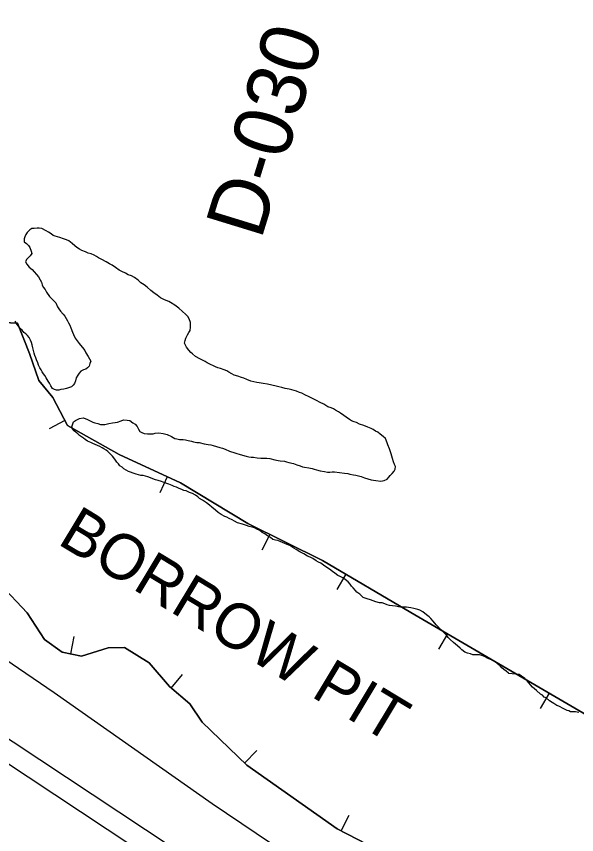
# Model space of a CAD drawing. Extents: x 3263578 to 3301413, y 764927 to 798602.
# Drawn here: x 3282551 to 3283343, y 780646 to 781803 of the extents above; entities that cross this region are included whole.
import ezdxf

# ---------------------------------------------------------------- set-up
doc = ezdxf.new("R2010")
doc.units = 0
for name, color, linetype in [('V-BORW-IDEN', 7, 'Continuous'), ('V-BORW-LINE', 7, 'Continuous'), ('V-LEVE-TOET', 7, 'Continuous'), ('V-RIVR-RANG-IDEN', 7, 'Continuous'), ('V-SITE-VEGE', 7, 'Continuous'), ('V-SURV-LINE', 7, 'Continuous')]:
    doc.layers.add(name, color=color, linetype=linetype)

msp = doc.modelspace()

# ---------------------------------------------------------------- linework, layer by layer
at = {"layer": 'V-BORW-LINE'}
for p, q in [((3282619.2, 781231.5), (3282597.1, 781219.8)), ((3282763.8, 781151.8), (3282753.3, 781129.2)), ((3282908.9, 781070.4), (3282897.8, 781048)), ((3283016.2, 781014.1), (3283003.5, 780992.5)), ((3283159.9, 780929.7), (3283147.3, 780908.1)), ((3282627.4, 780901.4), (3282632.3, 780926)), ((3282769.5, 780853.1), (3282785.6, 780872.2)), ((3283303.7, 780845.7), (3283291.1, 780824.1)), ((3282873.2, 780747), (3282890.7, 780764.9)), ((3283009.6, 780651.4), (3283021, 780673.6))]:
    msp.add_line(p, q, dxfattribs=at)
for points in [[(3281936.7, 781679), (3281970.5, 781688), (3282101.7, 781597.5), (3282317.6, 781460.6), (3282365.2, 781493), (3282394, 781492.1), (3282442.1, 781462.3), (3282458.7, 781427.8), (3282449.4, 781377.6), (3282437.8, 781319.2), (3282438.2, 781301.5), (3282456.7, 781289.2), (3282475.5, 781286.2), (3282490, 781341.3), (3282512.8, 781370.8), (3282552.3, 781369), (3282569.1, 781326.3), (3282582.3, 781288), (3282602, 781263.8), (3282622.9, 781224.4), (3282695.9, 781183.2), (3282782.6, 781143.1), (3282877.6, 781085.9), (3282983.5, 781033.3)], [(3282983.5, 781033.3), (3282877.6, 781085.9), (3282782.6, 781143.1), (3282695.9, 781183.2), (3282622.9, 781224.4), (3282602, 781263.8), (3282582.3, 781288), (3282569.1, 781326.3), (3282552.3, 781369), (3282512.8, 781370.8), (3282490, 781341.3), (3282475.5, 781286.2), (3282456.7, 781289.2), (3282438.2, 781301.5), (3282437.8, 781319.2), (3282449.4, 781377.6), (3282458.7, 781427.8), (3282442.1, 781462.3), (3282394, 781492.1), (3282365.2, 781493), (3282317.6, 781460.6), (3282101.7, 781597.5), (3281970.5, 781688), (3281936.7, 781679)], [(3282983.5, 781033.3), (3283108.4, 780959.8), (3283356.9, 780814.6), (3283428.4, 780772.9), (3283485.5, 780717.2), (3283537, 780681.4), (3283609.2, 780664), (3283697.2, 780660.9), (3283794.4, 780670.6), (3283906.6, 780663.8), (3283981.7, 780643.3)], [(3283981.7, 780643.3), (3283906.6, 780663.8), (3283794.4, 780670.6), (3283697.2, 780660.9), (3283609.2, 780664), (3283537, 780681.4), (3283485.5, 780717.2), (3283428.4, 780772.9), (3283356.9, 780814.6), (3283108.4, 780959.8), (3282983.5, 781033.3)], [(3282813.5, 780805.1), (3282795.8, 780830.9), (3282767, 780855.2), (3282738.3, 780888.9), (3282703.5, 780910.5), (3282680.4, 780909.9), (3282642.6, 780898.4), (3282615.3, 780903.8), (3282590.4, 780921.7), (3282566, 780959.5), (3282527.5, 781000.1)], [(3282527.5, 781000.1), (3282566, 780959.5), (3282590.4, 780921.7), (3282615.3, 780903.8), (3282642.6, 780898.4), (3282680.4, 780909.9), (3282703.5, 780910.5), (3282738.3, 780888.9), (3282767, 780855.2), (3282795.8, 780830.9), (3282813.5, 780805.1)], [(3283144.6, 780581.6), (3283004.1, 780654.2), (3282876.4, 780744), (3282813.5, 780805.1)], [(3282813.5, 780805.1), (3282876.4, 780744), (3283004.1, 780654.2), (3283144.6, 780581.6)]]:
    msp.add_lwpolyline(points, dxfattribs=at)
at = {"layer": 'V-LEVE-TOET'}
msp.add_lwpolyline([(3282972.3, 780592), (3282827.2, 780689.6), (3282604, 780846.6), (3282423.9, 780969.1), (3282234.6, 781089.3), (3282039.4, 781214), (3281861, 781327.2), (3281775.1, 781380.4), (3281661.9, 781445.9), (3281571.4, 781498), (3281456.3, 781581.8), (3281323.5, 781672.6), (3281178.8, 781772.9), (3281016.6, 781873.4), (3280802.7, 782020.5), (3280772.2, 782036.9), (3280719.9, 782063), (3280609.7, 782132.1), (3280537.9, 782178.1), (3280496.4, 782202.5)], dxfattribs=at)
at = {"layer": 'V-SITE-VEGE'}
for points in [[(3282930.8, 781276.7), (3282926, 781278.1), (3282921.7, 781279), (3282918, 781279.9), (3282911.6, 781281.3), (3282905.4, 781282.7), (3282899.3, 781283.9), (3282894, 781284.8), (3282890.5, 781285.4), (3282886.2, 781286.2), (3282881.9, 781287.1), (3282876.4, 781289.6), (3282872.1, 781291.3), (3282868.9, 781292.1), (3282863.8, 781294.1), (3282858.5, 781295.7), (3282855.1, 781297.4), (3282851.1, 781299.9), (3282848.2, 781301.5), (3282844.4, 781303.2), (3282839.1, 781305.1), (3282835.6, 781306), (3282832.2, 781307.4), (3282829.3, 781308.8), (3282825, 781310.7), (3282820.5, 781313.2), (3282817.3, 781314.8), (3282813.6, 781316.8), (3282810.1, 781318.7), (3282804, 781322), (3282799.5, 781325.5), (3282797.4, 781327.7), (3282794.2, 781330.7), (3282791.3, 781335), (3282788.2, 781341), (3282789.1, 781344.4), (3282790.2, 781347.9), (3282792.4, 781352.4), (3282794.6, 781356.1), (3282796.3, 781358.8), (3282796.6, 781363.3), (3282796.7, 781370), (3282794.9, 781375.1), (3282792.8, 781378.4), (3282789.6, 781381.6), (3282785.4, 781385.7), (3282780.1, 781390.1), (3282774.8, 781394.4), (3282768.7, 781398.3), (3282766.1, 781399.9), (3282762.6, 781401.3), (3282759.1, 781402.4), (3282754.6, 781404.9), (3282749.6, 781408.5), (3282745.1, 781411.8), (3282740.6, 781415.3), (3282735.6, 781419.9), (3282731.3, 781423.2), (3282726.8, 781426.2), (3282722.6, 781430), (3282717.8, 781433.6), (3282713.6, 781435.8), (3282708.8, 781437.5), (3282704.8, 781439.7), (3282699.5, 781442.2), (3282696, 781444.1), (3282691, 781447.9), (3282686.2, 781451.2), (3282682.2, 781453.1), (3282677.5, 781455.9), (3282671.6, 781458.9), (3282666.8, 781461.6), (3282663.9, 781463.3), (3282660.5, 781465.2), (3282656.5, 781466.9), (3282652.2, 781468), (3282648.2, 781470), (3282643.4, 781471.6), (3282639.7, 781473.6), (3282636.3, 781476), (3282633.3, 781478.5), (3282629.4, 781481.7), (3282624.6, 781485.6), (3282621.4, 781487), (3282617.2, 781488.4), (3282612.1, 781490), (3282605.7, 781492.3), (3282602.8, 781493.1), (3282599.6, 781495.3), (3282595.9, 781497.8), (3282592.7, 781499.4), (3282586.8, 781502.7), (3282583.1, 781503.3), (3282579.9, 781503.4), (3282575.9, 781502.9), (3282572.7, 781502.9), (3282569.7, 781501.1), (3282566.1, 781497.1), (3282564.2, 781494.5), (3282562.6, 781491.3), (3282561.5, 781488.1)], [(3282561.5, 781488.1), (3282561.9, 781484.1), (3282564.9, 781481.9), (3282567.8, 781478.9), (3282569.6, 781475.9), (3282571.7, 781471.1), (3282572.4, 781467.6), (3282570.2, 781464.4), (3282568, 781462), (3282564.8, 781458.9), (3282563.4, 781455.7), (3282565.2, 781452.4), (3282568.9, 781448.4), (3282572.9, 781444.8), (3282576, 781441.6), (3282578.9, 781437.8), (3282581.8, 781434.5), (3282584.4, 781430.5), (3282586.3, 781427.2), (3282587.3, 781423.5), (3282588.6, 781420.2), (3282591.2, 781416.7), (3282593.3, 781412.9), (3282597.5, 781407), (3282602.8, 781401.8), (3282606.5, 781398), (3282609, 781392.1), (3282610.9, 781389.4), (3282613.2, 781386.1), (3282616.7, 781381.8), (3282619, 781379.1), (3282620.8, 781375.8), (3282622.9, 781372.3), (3282624.2, 781369.4), (3282626.1, 781366.1), (3282627.4, 781362.6), (3282629.9, 781356.2), (3282631.2, 781352.9), (3282633.8, 781348.1), (3282636.4, 781344), (3282639.6, 781340.2), (3282641.4, 781337.8), (3282644.3, 781334.5), (3282647.2, 781330.5), (3282649, 781327.2), (3282652.2, 781321.8), (3282655.8, 781315.3), (3282654.7, 781312.1), (3282653.6, 781308.1), (3282651.4, 781305.8), (3282648.7, 781304.2), (3282645.5, 781302.9), (3282642, 781301.1), (3282639.5, 781298.2), (3282637.6, 781295.5), (3282635.4, 781291.8), (3282634.3, 781287.5), (3282632.6, 781283.8), (3282631, 781281.2), (3282628.5, 781279.1), (3282624.5, 781277.5), (3282621.3, 781276.5), (3282617.8, 781275.7), (3282613.7, 781275.3), (3282610.8, 781274.5), (3282607.6, 781274.3), (3282604.6, 781275.4), (3282601.7, 781276.8), (3282599.4, 781280.6), (3282597.5, 781284.1), (3282595.7, 781287.3), (3282592.8, 781291.6), (3282591, 781295.1), (3282588.9, 781297.6), (3282587.1, 781300.3), (3282585.5, 781303), (3282583.7, 781306), (3282582.1, 781309.7), (3282581.1, 781313), (3282579.3, 781317), (3282578.3, 781320), (3282576.7, 781323.5), (3282575.7, 781326.7), (3282574.7, 781330.2), (3282573.9, 781334), (3282572.9, 781338.5), (3282571.9, 781341.8), (3282570.6, 781345), (3282568.5, 781348.8), (3282566.4, 781351.5), (3282563.8, 781353.9), (3282561.4, 781356.1), (3282559, 781359.1), (3282556.6, 781361.3), (3282554.5, 781363.4), (3282551.6, 781367.2), (3282548.8, 781371.8)], [(3282833.5, 781194.9), (3282838.3, 781193.5), (3282842, 781192.1), (3282846, 781190.7), (3282852.1, 781187.9), (3282859.3, 781185.9), (3282862.5, 781184.8), (3282865.7, 781184), (3282870.2, 781182.3), (3282875.3, 781181.2), (3282879.3, 781180.3), (3282882.5, 781179.7), (3282885.7, 781179.4), (3282890.8, 781178.8), (3282896.1, 781178.4), (3282899.4, 781178.4), (3282904.7, 781178.3), (3282909, 781177.7), (3282915.9, 781176), (3282920.5, 781174.9), (3282923.7, 781174.3), (3282929.5, 781173.9), (3282932.7, 781173.1), (3282935.7, 781172), (3282942.3, 781170.5), (3282947.1, 781168.6), (3282951.7, 781167.2), (3282954.9, 781166), (3282958.1, 781165.5), (3282964.2, 781164.6), (3282968.8, 781163.7), (3282971.7, 781162.6), (3282975.1, 781161.5), (3282980, 781160.3), (3282986.1, 781159.4), (3282990.4, 781158.6), (3282993.6, 781158.5), (3282997.1, 781158.7), (3283000.3, 781158.7), (3283007.5, 781158), (3283014.7, 781157.1), (3283019, 781156.3), (3283022.2, 781155.4), (3283027.3, 781154.8), (3283030.5, 781154.2), (3283037.9, 781152.2), (3283042.7, 781150.6), (3283047.5, 781149.1), (3283052.3, 781147.7), (3283058.7, 781146.6), (3283066, 781145.7), (3283070.5, 781146.4), (3283074.8, 781148.7), (3283077.3, 781151.1), (3283079.2, 781153.5), (3283081.9, 781156.4), (3283084.9, 781159.8), (3283086.3, 781162.8), (3283086.6, 781166.2), (3283085.3, 781169.2), (3283083.8, 781173), (3283082.2, 781177.5), (3283080.5, 781184.5), (3283077.9, 781191.5), (3283075.8, 781196.9), (3283074.8, 781199.9), (3283072.2, 781205.8), (3283069, 781208.8), (3283064.8, 781212.1), (3283061.4, 781214.8), (3283058.4, 781216.5), (3283055, 781218.7), (3283052.1, 781220), (3283047.5, 781222), (3283041.7, 781224.2), (3283035.8, 781226.4), (3283031.6, 781228.4), (3283028.1, 781229.8), (3283024.4, 781231.2), (3283021.5, 781232.8), (3283016.7, 781236.4), (3283013.5, 781238.5), (3283009, 781241.8), (3283005.8, 781243.8), (3283001.6, 781246), (3282998.7, 781247.9), (3282995.7, 781249.3), (3282990.9, 781250.9), (3282988, 781252.8), (3282985.1, 781254.5), (3282980.3, 781257), (3282975, 781259.5), (3282969.4, 781262.5), (3282963.8, 781265.3), (3282959.3, 781267.5), (3282954, 781270), (3282950.8, 781271.1), (3282946.5, 781272.7), (3282940.1, 781274.7), (3282936.1, 781275.6), (3282930.8, 781276.7)], [(3282784.6, 781133.8), (3282780.6, 781135.4), (3282777.2, 781137.1), (3282773.7, 781138.2), (3282770.8, 781139.6), (3282766, 781141.5), (3282760.4, 781143.5), (3282755.9, 781145.2), (3282751.1, 781146.8), (3282747.1, 781147.7), (3282743.6, 781149.1), (3282740.4, 781150.2), (3282736.4, 781151.9), (3282733.2, 781152.7), (3282730, 781153.6), (3282726.5, 781153.9), (3282723.3, 781154.8), (3282719.9, 781155.6), (3282715.6, 781157), (3282711.9, 781158.4), (3282709, 781159.5), (3282706, 781161.2), (3282702.6, 781163.1), (3282700.2, 781165.3), (3282697, 781167.5), (3282694.9, 781170.2), (3282692.8, 781172.6), (3282689.7, 781176.9), (3282686.5, 781181), (3282684.1, 781183.4), (3282679.9, 781187.5), (3282677.5, 781189.7), (3282674.3, 781191.4), (3282671.7, 781193), (3282668.5, 781194.9), (3282665.3, 781196.3), (3282662.1, 781197.7), (3282658.9, 781198.8), (3282655.7, 781200.2), (3282651.2, 781202.4), (3282647.8, 781204.6), (3282645.4, 781206.5), (3282642.7, 781208.4), (3282640.1, 781210.3), (3282637.7, 781212.5), (3282635.3, 781214.4), (3282632.4, 781216.9), (3282629.8, 781219.6), (3282629, 781222.6), (3282630.1, 781225.5), (3282631.5, 781229.5), (3282634.2, 781231.3), (3282637.2, 781232.9), (3282639.9, 781234.4), (3282645, 781235.2), (3282647.9, 781234.3), (3282651.4, 781232.9), (3282654.1, 781231.3), (3282658.6, 781229.1), (3282661.5, 781228), (3282665.8, 781227.1), (3282669.8, 781226), (3282675.7, 781225.6), (3282681.3, 781227.4), (3282686.4, 781228.1), (3282690.4, 781228.6), (3282693.7, 781229.1), (3282698.8, 781231.2), (3282702, 781232.2), (3282707.1, 781232.1), (3282710.8, 781231.5), (3282715.3, 781228.2), (3282718.8, 781226.3), (3282721.4, 781223.1), (3282723.2, 781219), (3282725.3, 781216), (3282728, 781214.4), (3282731.4, 781213.3), (3282736, 781212.7), (3282739.7, 781212.6), (3282744, 781212.8), (3282747, 781213.6), (3282752.1, 781213.8), (3282758.2, 781212.9), (3282763.6, 781211.7), (3282769.7, 781208.7), (3282774.7, 781206.2), (3282777.6, 781205.4), (3282781.1, 781204.8), (3282786.2, 781204.4), (3282789.9, 781204.1), (3282793.4, 781203), (3282798.2, 781202.1), (3282801.2, 781201.3), (3282805.7, 781200.4), (3282808.9, 781200.3), (3282816.1, 781198.4), (3282821.7, 781197.5), (3282825.7, 781196.9), (3282828.9, 781196), (3282833.5, 781194.9)], [(3283168.6, 780917.6), (3283163.9, 780921.7), (3283161.2, 780924.4), (3283158.6, 780927.7), (3283154.9, 780931.5), (3283152.5, 780933.9), (3283149.9, 780936.6), (3283147.2, 780939.3), (3283144.1, 780942.6), (3283139.9, 780947.8), (3283136.7, 780951.3), (3283134.1, 780953.7), (3283130.4, 780956.7), (3283125.1, 780960.8), (3283121.1, 780963.3), (3283117.9, 780964.1), (3283112.6, 780965.8), (3283108.3, 780966.4), (3283105.1, 780967), (3283101.9, 780967.6), (3283098.1, 780967.7), (3283093.8, 780967.4), (3283090.6, 780968), (3283086.6, 780968.9), (3283082.1, 780969.5), (3283078.1, 780970.1), (3283074.9, 780970.9), (3283071.7, 780972.1), (3283067.7, 780973.5), (3283063.9, 780973.5), (3283058.6, 780975.2), (3283055.1, 780976.3), (3283051.4, 780977.7), (3283046.4, 780979.1), (3283041, 780981.1), (3283038.6, 780983.3), (3283036, 780986), (3283032, 780988.7), (3283029.9, 780990.9), (3283026.8, 780994.7), (3283024.4, 780997.4), (3283022.6, 780999.8), (3283019.7, 781003.4), (3283015.4, 781006.6), (3283012.3, 781009.1), (3283008.5, 781011), (3283005.1, 781012.4), (3283000.8, 781015.4), (3282997.7, 781018.1), (3282993.4, 781021.4), (3282989.7, 781023.6), (3282984.7, 781026.9), (3282981, 781029.6), (3282977.8, 781031.3), (3282974.6, 781033.2), (3282969.8, 781036.2), (3282965.8, 781038.2), (3282962.1, 781039.8), (3282956.8, 781042.8), (3282951.2, 781045.9), (3282946.2, 781049.2), (3282943, 781051.1), (3282937.1, 781054.7), (3282933.2, 781056.3), (3282930, 781057.7), (3282923.3, 781060.5), (3282920.4, 781061.9), (3282916.9, 781062.4), (3282913.4, 781063.3), (3282909.7, 781065.8), (3282905.8, 781068.5), (3282901.8, 781071), (3282898.3, 781073.2), (3282894.9, 781075.9), (3282890.6, 781077.8), (3282887.4, 781079.5), (3282884, 781080.6), (3282879.7, 781081.7), (3282876, 781082.9), (3282870.1, 781085.1), (3282863.2, 781086.8), (3282858.9, 781089), (3282855.5, 781090.9), (3282851.5, 781093.1), (3282848, 781094.8), (3282845.1, 781095.9), (3282840.3, 781098.7), (3282836.1, 781101.4), (3282831.9, 781104.7), (3282826.8, 781108.8), (3282823.7, 781111.5), (3282819.2, 781115), (3282813.9, 781118.9), (3282809.6, 781121.3), (3282807, 781123.3), (3282803.8, 781125.7), (3282799.5, 781128.2), (3282795.5, 781129.8), (3282790.5, 781131.8), (3282787.5, 781132.6), (3282784.6, 781133.8)], [(3283345.6, 780818.8), (3283340.9, 780819.5), (3283333.9, 780819.6), (3283331.5, 780820.8), (3283329.2, 780821.4), (3283326.3, 780822.6), (3283324.5, 780823.8), (3283317.5, 780827.5), (3283314.6, 780828.7), (3283310.5, 780831.1), (3283308.2, 780832.9), (3283304.1, 780835.3), (3283299.4, 780839.5), (3283296.5, 780840.2), (3283294.2, 780843.1), (3283291.3, 780844.4), (3283286, 780849.7), (3283280.2, 780854.5), (3283277.3, 780857.5), (3283272.7, 780863.5), (3283269.2, 780866.5), (3283264.5, 780870.1), (3283261.6, 780872.5), (3283247, 780873.9), (3283246.4, 780874.4), (3283243, 780877.1), (3283239.8, 780879.6), (3283236.9, 780881.8), (3283234.3, 780884.5), (3283230.8, 780887.2), (3283227.4, 780890.2), (3283224.7, 780892.1), (3283221, 780893.5), (3283216.2, 780895.5), (3283213.3, 780897.1), (3283208.5, 780899.3), (3283205.3, 780900.2), (3283201.6, 780900.2), (3283195.9, 780900.3), (3283192.5, 780901.7), (3283188.2, 780902.3), (3283184.5, 780904), (3283180.5, 780907.3), (3283177.9, 780909.4), (3283174.4, 780913), (3283171.3, 780915.4), (3283168.6, 780917.6)]]:
    msp.add_lwpolyline(points, dxfattribs=at)
at = {"layer": 'V-SURV-LINE'}
for points in [[(3282359.9, 780900.1), (3284221.3, 779667)], [(3284204.7, 779642), (3282343.3, 780875.1)]]:
    msp.add_lwpolyline(points, dxfattribs=at)

# ---------------------------------------------------------------- texts
at = {"layer": 'V-BORW-IDEN'}
msp.add_text('BORROW PIT', height=64, rotation=328.9533, dxfattribs=at).set_placement((3282607, 781057.9))
at = {"layer": 'V-RIVR-RANG-IDEN'}
msp.add_text('D-030', height=83, rotation=72.9039, dxfattribs=at).set_placement((3282896.4, 781485.6))

doc.saveas('drawing.dxf')
